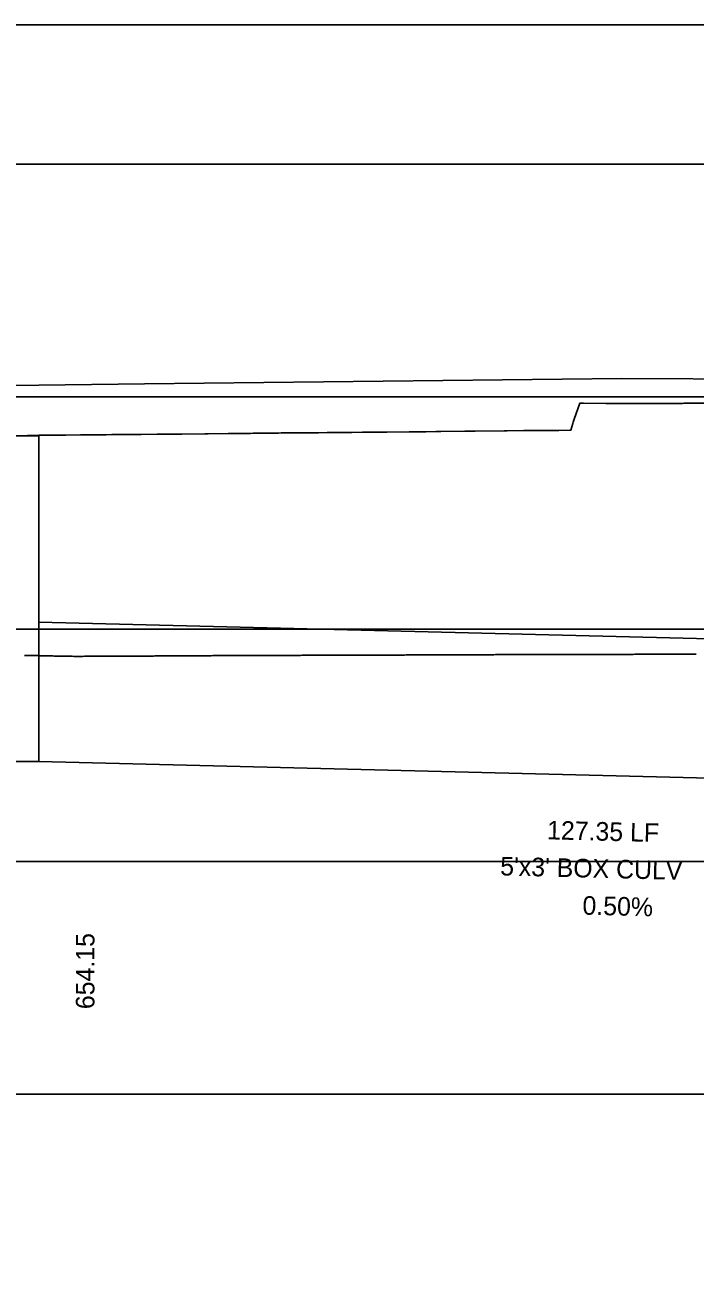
# Model space of a CAD drawing. Extents: x 2252703 to 2264864, y 13787568 to 13790989.
# Drawn here: x 2258038.3 to 2258110.4, y 13790832 to 13790965.5 of the extents above; entities that cross this region are included whole.
import ezdxf

# ---------------------------------------------------------------- set-up
doc = ezdxf.new("R2010")
doc.units = 0
for name, color, linetype in [('blank4', 7, 'Continuous'), ('D_DRN_PROF_HGL', 7, 'Continuous'), ('D_PROF_1', 7, 'Continuous'), ('D_PROF_NOTES_1', 7, 'Continuous'), ('Drain_PipeInside', 7, 'Continuous'), ('E_Terrain', 7, 'Continuous'), ('Inlet', 7, 'Continuous'), ('z - Construction', 7, 'Continuous')]:
    doc.layers.add(name, color=color, linetype=linetype)

msp = doc.modelspace()

# ---------------------------------------------------------------- linework, layer by layer
at = {"layer": 'blank4'}
msp.add_lwpolyline([(2257912.03, 13790700.51), (2257912.03, 13790965.51), (2261066.03, 13790965.51), (2261066.03, 13790700.51)], close=True, dxfattribs=at)
at = {"layer": 'D_DRN_PROF_HGL'}
msp.add_lwpolyline([(2258038.22, 13790897.68), (2258038.38, 13790897.68), (2258038.54, 13790897.68), (2258038.7, 13790897.68), (2258038.86, 13790897.67), (2258039.02, 13790897.67), (2258039.18, 13790897.67), (2258039.34, 13790897.66), (2258039.5, 13790897.66), (2258039.66, 13790897.66), (2258039.82, 13790897.65), (2258039.98, 13790897.65), (2258040.14, 13790897.65), (2258040.3, 13790897.65), (2258040.46, 13790897.64), (2258040.62, 13790897.64), (2258040.78, 13790897.64), (2258040.94, 13790897.63), (2258041.1, 13790897.63), (2258041.26, 13790897.63), (2258041.42, 13790897.62), (2258041.58, 13790897.62), (2258041.75, 13790897.62), (2258041.91, 13790897.62), (2258042.07, 13790897.61), (2258042.23, 13790897.61), (2258042.39, 13790897.61), (2258042.55, 13790897.6), (2258042.72, 13790897.6), (2258042.88, 13790897.6), (2258043.04, 13790897.59), (2258043.2, 13790897.59), (2258043.36, 13790897.59), (2258043.53, 13790897.58), (2258043.69, 13790897.58), (2258043.85, 13790897.58), (2258044.01, 13790897.58), (2258044.18, 13790897.58), (2258044.34, 13790897.58), (2258044.5, 13790897.58), (2258044.67, 13790897.59), (2258044.83, 13790897.59), (2258044.99, 13790897.59), (2258045.15, 13790897.59), (2258045.32, 13790897.59), (2258045.48, 13790897.59), (2258045.65, 13790897.59), (2258045.81, 13790897.59), (2258045.97, 13790897.59), (2258046.14, 13790897.59), (2258046.3, 13790897.59), (2258046.46, 13790897.6), (2258046.63, 13790897.6), (2258046.79, 13790897.6), (2258046.96, 13790897.6), (2258047.12, 13790897.6), (2258047.29, 13790897.6), (2258047.45, 13790897.6), (2258047.61, 13790897.6), (2258047.78, 13790897.6), (2258047.94, 13790897.6), (2258048.11, 13790897.6), (2258048.27, 13790897.61), (2258048.44, 13790897.61), (2258048.6, 13790897.61), (2258048.77, 13790897.61), (2258048.93, 13790897.61), (2258049.1, 13790897.61), (2258049.26, 13790897.61), (2258049.43, 13790897.61), (2258049.6, 13790897.61), (2258049.76, 13790897.61), (2258049.93, 13790897.61), (2258050.09, 13790897.61), (2258050.26, 13790897.62), (2258050.42, 13790897.62), (2258050.59, 13790897.62), (2258050.76, 13790897.62), (2258050.92, 13790897.62), (2258051.09, 13790897.62), (2258051.26, 13790897.62), (2258051.42, 13790897.62), (2258051.59, 13790897.62), (2258051.75, 13790897.62), (2258051.92, 13790897.62), (2258052.09, 13790897.62), (2258052.26, 13790897.63), (2258052.42, 13790897.63), (2258052.59, 13790897.63), (2258052.76, 13790897.63), (2258052.92, 13790897.63), (2258053.09, 13790897.63), (2258053.26, 13790897.63), (2258053.43, 13790897.63), (2258053.59, 13790897.63), (2258053.76, 13790897.63), (2258053.93, 13790897.63), (2258054.1, 13790897.63), (2258054.26, 13790897.64), (2258054.43, 13790897.64), (2258054.6, 13790897.64), (2258054.77, 13790897.64), (2258054.93, 13790897.64), (2258055.1, 13790897.64), (2258055.27, 13790897.64), (2258055.44, 13790897.64), (2258055.61, 13790897.64), (2258055.78, 13790897.64), (2258055.94, 13790897.64), (2258056.11, 13790897.64), (2258056.28, 13790897.65), (2258056.45, 13790897.65), (2258056.62, 13790897.65), (2258056.79, 13790897.65), (2258056.96, 13790897.65), (2258057.13, 13790897.65), (2258057.29, 13790897.65), (2258057.46, 13790897.65), (2258057.63, 13790897.65), (2258057.8, 13790897.65), (2258057.97, 13790897.65), (2258058.14, 13790897.65), (2258058.31, 13790897.65), (2258058.48, 13790897.66), (2258058.65, 13790897.66), (2258058.82, 13790897.66), (2258058.99, 13790897.66), (2258059.16, 13790897.66), (2258059.33, 13790897.66), (2258059.5, 13790897.66), (2258059.67, 13790897.66), (2258059.84, 13790897.66), (2258060.01, 13790897.66), (2258060.18, 13790897.66), (2258060.35, 13790897.66), (2258060.52, 13790897.66), (2258060.69, 13790897.66), (2258060.86, 13790897.67), (2258061.03, 13790897.67), (2258061.2, 13790897.67), (2258061.37, 13790897.67), (2258061.54, 13790897.67), (2258061.71, 13790897.67), (2258061.88, 13790897.67), (2258062.06, 13790897.67), (2258062.23, 13790897.67), (2258062.4, 13790897.67), (2258062.57, 13790897.67), (2258062.74, 13790897.67), (2258062.91, 13790897.67), (2258063.08, 13790897.68), (2258063.25, 13790897.68), (2258063.43, 13790897.68), (2258063.6, 13790897.68), (2258063.77, 13790897.68), (2258063.94, 13790897.68), (2258064.11, 13790897.68), (2258064.28, 13790897.68), (2258064.46, 13790897.68), (2258064.63, 13790897.68), (2258064.8, 13790897.68), (2258064.97, 13790897.68), (2258065.14, 13790897.68), (2258065.32, 13790897.68), (2258065.49, 13790897.68), (2258065.66, 13790897.69), (2258065.83, 13790897.69), (2258066, 13790897.69), (2258066.18, 13790897.69), (2258066.35, 13790897.69), (2258066.52, 13790897.69), (2258066.69, 13790897.69), (2258066.87, 13790897.69), (2258067.04, 13790897.69), (2258067.21, 13790897.69), (2258067.39, 13790897.69), (2258067.56, 13790897.69), (2258067.73, 13790897.69), (2258067.91, 13790897.69), (2258068.08, 13790897.7), (2258068.25, 13790897.7), (2258068.42, 13790897.7), (2258068.6, 13790897.7), (2258068.77, 13790897.7), (2258068.94, 13790897.7), (2258069.12, 13790897.7), (2258069.29, 13790897.7), (2258069.47, 13790897.7), (2258069.64, 13790897.7), (2258069.81, 13790897.7), (2258069.99, 13790897.7), (2258070.16, 13790897.7), (2258070.33, 13790897.7), (2258070.51, 13790897.7), (2258070.68, 13790897.71), (2258070.86, 13790897.71), (2258071.03, 13790897.71), (2258071.2, 13790897.71), (2258071.38, 13790897.71), (2258071.55, 13790897.71), (2258071.73, 13790897.71), (2258071.9, 13790897.71), (2258072.08, 13790897.71), (2258072.25, 13790897.71), (2258072.42, 13790897.71), (2258072.6, 13790897.71), (2258072.77, 13790897.71), (2258072.95, 13790897.71), (2258073.12, 13790897.71), (2258073.3, 13790897.71), (2258073.47, 13790897.72), (2258073.65, 13790897.72), (2258073.82, 13790897.72), (2258074, 13790897.72), (2258074.17, 13790897.72), (2258074.35, 13790897.72), (2258074.52, 13790897.72), (2258074.7, 13790897.72), (2258074.87, 13790897.72), (2258075.05, 13790897.72), (2258075.22, 13790897.72), (2258075.4, 13790897.72), (2258075.58, 13790897.72), (2258075.75, 13790897.72), (2258075.93, 13790897.72), (2258076.1, 13790897.72), (2258076.28, 13790897.73), (2258076.45, 13790897.73), (2258076.63, 13790897.73), (2258076.81, 13790897.73), (2258076.98, 13790897.73), (2258077.16, 13790897.73), (2258077.33, 13790897.73), (2258077.51, 13790897.73), (2258077.69, 13790897.73), (2258077.86, 13790897.73), (2258078.04, 13790897.73), (2258078.21, 13790897.73), (2258078.39, 13790897.73), (2258078.57, 13790897.73), (2258078.74, 13790897.73), (2258078.92, 13790897.73), (2258079.1, 13790897.73), (2258079.27, 13790897.74), (2258079.45, 13790897.74), (2258079.63, 13790897.74), (2258079.8, 13790897.74), (2258079.98, 13790897.74), (2258080.16, 13790897.74), (2258080.33, 13790897.74), (2258080.51, 13790897.74), (2258080.69, 13790897.74), (2258080.86, 13790897.74), (2258081.04, 13790897.74), (2258081.22, 13790897.74), (2258081.4, 13790897.74), (2258081.57, 13790897.74), (2258081.75, 13790897.74), (2258081.93, 13790897.74), (2258082.1, 13790897.74), (2258082.28, 13790897.75), (2258082.46, 13790897.75), (2258082.64, 13790897.75), (2258082.81, 13790897.75), (2258082.99, 13790897.75), (2258083.17, 13790897.75), (2258083.35, 13790897.75), (2258083.52, 13790897.75), (2258083.7, 13790897.75), (2258083.88, 13790897.75), (2258084.06, 13790897.75), (2258084.24, 13790897.75), (2258084.41, 13790897.75), (2258084.59, 13790897.75), (2258084.77, 13790897.75), (2258084.95, 13790897.75), (2258085.13, 13790897.75), (2258085.3, 13790897.75), (2258085.48, 13790897.76), (2258085.66, 13790897.76), (2258085.84, 13790897.76), (2258086.02, 13790897.76), (2258086.2, 13790897.76), (2258086.37, 13790897.76), (2258086.55, 13790897.76), (2258086.73, 13790897.76), (2258086.91, 13790897.76), (2258087.09, 13790897.76), (2258087.27, 13790897.76), (2258087.45, 13790897.76), (2258087.62, 13790897.76), (2258087.8, 13790897.76), (2258087.98, 13790897.76), (2258088.16, 13790897.76), (2258088.34, 13790897.76), (2258088.52, 13790897.76), (2258088.7, 13790897.76), (2258088.88, 13790897.77), (2258089.06, 13790897.77), (2258089.24, 13790897.77), (2258089.41, 13790897.77), (2258089.59, 13790897.77), (2258089.77, 13790897.77), (2258089.95, 13790897.77), (2258090.13, 13790897.77), (2258090.31, 13790897.77), (2258090.49, 13790897.77), (2258090.67, 13790897.77), (2258090.85, 13790897.77), (2258091.03, 13790897.77), (2258091.21, 13790897.77), (2258091.39, 13790897.77), (2258091.57, 13790897.77), (2258091.75, 13790897.77), (2258091.93, 13790897.77), (2258092.11, 13790897.77), (2258092.29, 13790897.77), (2258092.47, 13790897.78), (2258092.65, 13790897.78), (2258092.83, 13790897.78), (2258093.01, 13790897.78), (2258093.19, 13790897.78), (2258093.37, 13790897.78), (2258093.55, 13790897.78), (2258093.73, 13790897.78), (2258093.91, 13790897.78), (2258094.09, 13790897.78), (2258094.27, 13790897.78), (2258094.45, 13790897.78), (2258094.63, 13790897.78), (2258094.81, 13790897.78), (2258094.99, 13790897.78), (2258095.17, 13790897.78), (2258095.35, 13790897.78), (2258095.53, 13790897.78), (2258095.71, 13790897.78), (2258095.89, 13790897.78), (2258096.07, 13790897.79), (2258096.25, 13790897.79), (2258096.44, 13790897.79), (2258096.62, 13790897.79), (2258096.8, 13790897.79), (2258096.98, 13790897.79), (2258097.16, 13790897.79), (2258097.34, 13790897.79), (2258097.52, 13790897.79), (2258097.7, 13790897.79), (2258097.88, 13790897.79), (2258098.06, 13790897.79), (2258098.25, 13790897.79), (2258098.43, 13790897.79), (2258098.61, 13790897.79), (2258098.79, 13790897.79), (2258098.97, 13790897.79), (2258099.15, 13790897.79), (2258099.33, 13790897.79), (2258099.51, 13790897.79), (2258099.7, 13790897.79), (2258099.88, 13790897.8), (2258100.06, 13790897.8), (2258100.24, 13790897.8), (2258100.42, 13790897.8), (2258100.6, 13790897.8), (2258100.79, 13790897.8), (2258100.97, 13790897.8), (2258101.15, 13790897.8), (2258101.33, 13790897.8), (2258101.51, 13790897.8), (2258101.69, 13790897.8), (2258101.88, 13790897.8), (2258102.06, 13790897.8), (2258102.24, 13790897.8), (2258102.42, 13790897.8), (2258102.6, 13790897.8), (2258102.79, 13790897.8), (2258102.97, 13790897.8), (2258103.15, 13790897.8), (2258103.33, 13790897.8), (2258103.52, 13790897.8), (2258103.7, 13790897.8), (2258103.88, 13790897.81), (2258104.06, 13790897.81), (2258104.24, 13790897.81), (2258104.43, 13790897.81), (2258104.61, 13790897.81), (2258104.79, 13790897.81), (2258104.97, 13790897.81), (2258105.16, 13790897.81), (2258105.34, 13790897.81), (2258105.52, 13790897.81), (2258105.71, 13790897.81), (2258105.89, 13790897.81), (2258106.07, 13790897.81), (2258106.25, 13790897.81), (2258106.44, 13790897.81), (2258106.62, 13790897.81), (2258106.8, 13790897.81), (2258106.98, 13790897.81), (2258107.17, 13790897.81), (2258107.35, 13790897.81), (2258107.53, 13790897.81), (2258107.72, 13790897.81), (2258107.9, 13790897.81), (2258108.08, 13790897.82), (2258108.27, 13790897.82), (2258108.45, 13790897.82), (2258108.63, 13790897.82), (2258108.82, 13790897.82), (2258109, 13790897.82), (2258109.18, 13790897.82), (2258109.37, 13790897.82), (2258109.55, 13790897.82), (2258109.73, 13790897.82), (2258109.92, 13790897.82), (2258110.1, 13790897.82), (2258110.28, 13790897.82), (2258110.47, 13790897.82)], dxfattribs=at)
at = {"layer": 'D_PROF_1'}
msp.add_lwpolyline([(2258035.75, 13790921.29), (2258038.55, 13790921.33), (2258038.87, 13790921.34), (2258039.75, 13790921.36), (2258039.75, 13790921.36), (2258042.09, 13790921.38), (2258042.48, 13790921.38), (2258042.67, 13790921.38), (2258044.25, 13790921.4), (2258045.59, 13790921.41), (2258045.76, 13790921.41), (2258046.78, 13790921.42), (2258046.91, 13790921.42), (2258047, 13790921.42), (2258047.61, 13790921.43), (2258047.83, 13790921.43), (2258049.5, 13790921.45), (2258049.62, 13790921.45), (2258050.51, 13790921.46), (2258050.76, 13790921.46), (2258052.51, 13790921.48), (2258052.62, 13790921.48), (2258053.33, 13790921.49), (2258053.43, 13790921.49), (2258054.08, 13790921.49), (2258054.17, 13790921.49), (2258054.77, 13790921.5), (2258055.15, 13790921.5), (2258057.62, 13790921.53), (2258057.97, 13790921.53), (2258060.14, 13790921.55), (2258060.28, 13790921.55), (2258061.11, 13790921.56), (2258061.3, 13790921.56), (2258062.45, 13790921.57), (2258062.47, 13790921.57), (2258062.54, 13790921.57), (2258062.84, 13790921.58), (2258064.52, 13790921.59), (2258064.67, 13790921.59), (2258065.48, 13790921.6), (2258065.54, 13790921.6), (2258065.83, 13790921.61), (2258065.86, 13790921.61), (2258066.07, 13790921.61), (2258066.52, 13790921.61), (2258068.84, 13790921.63), (2258068.97, 13790921.64), (2258069.67, 13790921.64), (2258069.85, 13790921.64), (2258070.77, 13790921.65), (2258071.07, 13790921.66), (2258072.58, 13790921.67), (2258072.68, 13790921.67), (2258073.23, 13790921.68), (2258073.45, 13790921.68), (2258074.59, 13790921.69), (2258074.83, 13790921.69), (2258076.07, 13790921.7), (2258076.17, 13790921.7), (2258076.74, 13790921.71), (2258077.19, 13790921.71), (2258079.61, 13790921.74), (2258080.09, 13790921.74), (2258080.17, 13790921.74), (2258081.24, 13790921.75), (2258081.4, 13790921.75), (2258082.46, 13790921.76), (2258082.61, 13790921.77), (2258082.97, 13790921.77), (2258083.02, 13790921.77), (2258085.6, 13790921.79), (2258085.89, 13790921.8), (2258086.44, 13790921.8), (2258086.5, 13790921.8), (2258086.7, 13790921.81), (2258086.72, 13790921.81), (2258089.82, 13790921.84), (2258090.04, 13790921.84), (2258090.12, 13790921.84), (2258090.13, 13790921.84), (2258091.94, 13790921.86), (2258092.03, 13790921.86), (2258092.61, 13790921.86), (2258092.64, 13790921.86), (2258093.58, 13790921.87), (2258093.62, 13790921.87), (2258094.53, 13790921.88), (2258094.55, 13790921.88), (2258094.91, 13790921.88), (2258094.92, 13790921.88), (2258095.69, 13790921.89), (2258095.7, 13790921.89), (2258096.89, 13790921.9), (2258096.89, 13790921.9), (2258096.98, 13790921.9), (2258097.21, 13790922.64), (2258097.26, 13790922.78), (2258097.36, 13790923.11), (2258097.95, 13790924.81), (2258098.35, 13790924.8), (2258100.75, 13790924.78), (2258101.86, 13790924.77), (2258101.87, 13790924.77), (2258102.67, 13790924.77), (2258102.68, 13790924.77), (2258103.04, 13790924.77), (2258103.1, 13790924.77), (2258105.42, 13790924.77), (2258105.44, 13790924.77), (2258105.95, 13790924.77), (2258106.03, 13790924.77), (2258107.96, 13790924.78), (2258108.01, 13790924.78), (2258109.02, 13790924.79), (2258109.15, 13790924.8), (2258111.86, 13790924.83)], dxfattribs=at)
at = {"layer": 'Drain_PipeInside'}
for p, q in [((2258039.75, 13790901.28), (2258167.1, 13790898.09)), ((2258039.75, 13790886.28), (2258167.1, 13790883.09))]:
    msp.add_line(p, q, dxfattribs=at)
at = {"layer": 'E_Terrain'}
msp.add_lwpolyline([(2257912.03, 13790918.85), (2257912.85, 13790918.87), (2257916.74, 13790924.34), (2257917.27, 13790924.5), (2257917.38, 13790924.97), (2257927.53, 13790925.73), (2257931.04, 13790925.9), (2257939.15, 13790926.11), (2257950.87, 13790926.84), (2258000.4, 13790926.04), (2258031.75, 13790926.72), (2258031.75, 13790926.72), (2258035.75, 13790926.73), (2258035.75, 13790926.73), (2258039.75, 13790926.75), (2258039.75, 13790926.75), (2258051.14, 13790926.91), (2258102.49, 13790927.48), (2258117.81, 13790927.41), (2258167.1, 13790928.54), (2258167.1, 13790928.54), (2258171.1, 13790928.56), (2258171.1, 13790928.56), (2258175.1, 13790928.59)], dxfattribs=at)
at = {"layer": 'Inlet'}
msp.add_lwpolyline([(2258031.75, 13790921.29), (2258039.75, 13790921.29), (2258039.75, 13790886.28), (2258031.75, 13790886.28)], close=True, dxfattribs=at)
at = {"layer": 'z - Construction'}
for p, q in [((2257912.03, 13790950.51), (2261066.03, 13790950.51)), ((2257912.03, 13790925.51), (2261066.03, 13790925.51)), ((2257912.03, 13790900.51), (2261066.03, 13790900.51)), ((2257912.03, 13790875.51), (2261066.03, 13790875.51)), ((2257912.03, 13790850.51), (2261066.03, 13790850.51))]:
    msp.add_line(p, q, dxfattribs=at)

# ---------------------------------------------------------------- texts
at = {"layer": 'D_PROF_NOTES_1'}
for s, rotation, p in [('127.35 LF', 358.5679, (2258094.42, 13790877.91)), ("5'x3' BOX CULV", 358.5679, (2258089.38, 13790874.03)), ('0.50%', 358.5679, (2258098.23, 13790869.81)), ('654.15', 90, (2258045.75, 13790859.64))]:
    msp.add_text(s, height=2, rotation=rotation, dxfattribs=at).set_placement(p)

doc.saveas('drawing.dxf')
